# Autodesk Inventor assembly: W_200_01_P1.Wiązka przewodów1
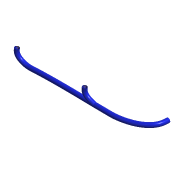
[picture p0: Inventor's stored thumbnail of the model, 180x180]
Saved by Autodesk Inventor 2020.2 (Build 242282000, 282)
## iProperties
Created: 2014-09
Part Number: W_200_01_P1.Wiązka przewodów1
Document SubType Name: Assembly
Designer: F.Stasiak
Catalog Web Link: www.expertbooks.pl
Manager: www.cadconsulting.pl
Company: Fabian Stasiak CAD Consulting
ParentFileIdentifier: 5|1|0|0|30|1|0|0|80|0|65|0|84|0|72|0|83|0|59|0|67|0|58|0|92|0|90|0|98|0|105|0|243|0|114|0|32|0|7|1|119|0|105|0|99|0|122|0|101|0|68|1|32|0|65|0|73|0|32|0|50|0|48
HarnessSettings: <HarnessSettings><Defaults><Segments><Diameter value="0.200 in" fromwires="True"/><Offset value="0.100 in"/><ColorStyle value="Niebieska - farba ścienna - lśnią
Author: F.Stasiak
Subject: Zbiór ćwiczeń. Autodesk Inventor 2020. Kurs Professional
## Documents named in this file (2)
- C:\2020_Kurs_Professional\R2 Wiązki\W_200_01_P1\AIP\przewody i wiązki przewodów\W_200_01_P1.Wiązka przewodów1.iam
- C:\2020_Kurs_Professional\R2 Wiązki\W_200_01_P1\AIP\przewody i wiązki przewodów\W_200_01_P1.Wiązka przewodów1.ipt
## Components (1 placed, 1 different names)
1. Wiązka przewodów1
